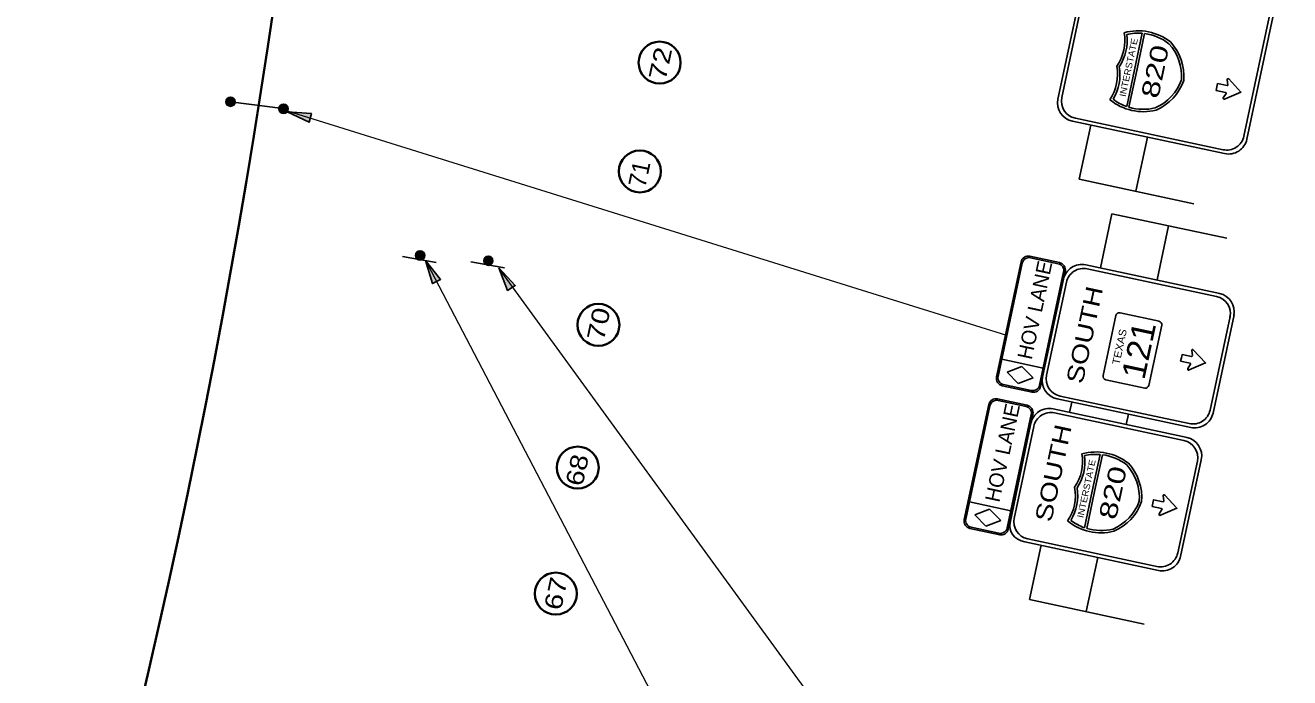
# Model space of a CAD drawing. Extents: x 2363411 to 2369702, y 6977197 to 6988655.
# Drawn here: x 2366110 to 2367124, y 6983553 to 6984077 of the extents above; entities that cross this region are included whole.
import ezdxf
from ezdxf.enums import TextEntityAlignment as Align

# ---------------------------------------------------------------- set-up
doc = ezdxf.new("R2010")
doc.units = 0
doc.header["$LTSCALE"] = 5.6
for name, color, linetype, lineweight in [('1', 7, 'Continuous', 25), ('17', 7, 'Continuous', 35), ('48', 7, 'Continuous', 25)]:
    doc.layers.add(name, color=color, linetype=linetype, lineweight=lineweight)

msp = doc.modelspace()

# ---------------------------------------------------------------- hatches: boundary and pattern name
at = {"layer": '1'}
for points in [[(2366276.795, 6984018.496, 1), (2366272.847, 6984012.162, 1)], [(2366319.296, 6984012.83, 1), (2366315.348, 6984006.496, 1)], [(2366320.148, 6984007.141), (2366337.866, 6983998.922), (2366339.646, 6984005.905)], [(2366428.953, 6983895.063, 1), (2366424.471, 6983889.095, 1)], [(2366430.991, 6983888.125), (2366436.822, 6983869.485), (2366443.188, 6983872.863)], [(2366483.682, 6983890.837, 1), (2366479.199, 6983884.87, 1)], [(2366489.737, 6983882.258), (2366496.901, 6983864.088), (2366503.005, 6983867.917)]]:
    msp.add_hatch(color=256, dxfattribs=at).paths.add_polyline_path(points)

# ---------------------------------------------------------------- linework, layer by layer
for p, q in [((2366937.872, 6984017.444), (2366972.227, 6984178.958)), ((2366941.013, 6984018.692), (2366974.591, 6984176.538)), ((2367120.468, 6984145.521), (2367086.899, 6983987.669)), ((2367123.601, 6984146.769), (2367089.253, 6983985.25)), ((2367005.449, 6984070.162), (2366999.21, 6984040.818)), ((2367007.339, 6984069.953), (2367001.059, 6984040.426)), ((2366992.972, 6984011.475), (2366999.21, 6984040.818)), ((2366994.781, 6984010.878), (2367001.059, 6984040.426)), ((2367065.825, 6984029.94), (2367073.428, 6984028.324)), ((2367074.048, 6984028.904), (2367073.471, 6984033.001)), ((2366274.821, 6984015.329), (2366316.854, 6984009.754)), ((2367070.386, 6984018.494), (2367072.577, 6984022.03)), ((2366949.436, 6983999.656), (2367071.475, 6983973.694)), ((2367070.226, 6983976.833), (2366951.84, 6984002.012)), ((2366954.911, 6983953.23), (2366964.242, 6983996.607)), ((2367000.271, 6983943.473), (2367009.6, 6983986.85)), ((2366954.911, 6983953.23), (2367046.841, 6983933.457)), ((2366981.19, 6983925.466), (2366971.979, 6983882.064)), ((2366981.19, 6983925.466), (2367073.175, 6983905.944)), ((2367026.577, 6983915.833), (2367017.365, 6983872.432)), ((2366412.725, 6983891.166), (2366439.68, 6983886.414)), ((2366467.454, 6983886.94), (2366494.408, 6983882.189)), ((2366960.122, 6983884.518), (2367067.7, 6983861.527)), ((2366925.607, 6983794.815), (2366942.328, 6983872.989)), ((2366961.375, 6983881.384), (2367064.906, 6983859.258)), ((2366928.748, 6983796.06), (2366944.687, 6983870.568)), ((2366984.29, 6983843.899), (2366973.996, 6983795.741)), ((2367018.859, 6983839.378), (2366987.625, 6983846.058)), ((2367075.835, 6983843.158), (2367059.789, 6983768.062)), ((2367079.003, 6983844.551), (2367062.143, 6983765.64)), ((2367010.729, 6983787.892), (2367021.025, 6983836.042)), ((2367037.392, 6983812.757), (2367044.995, 6983811.141)), ((2367045.615, 6983811.721), (2367045.038, 6983815.818)), ((2367041.953, 6983801.311), (2367044.144, 6983804.847)), ((2366976.162, 6983792.405), (2367007.394, 6983785.726)), ((2366937.154, 6983777.017), (2367044.353, 6983754.102)), ((2367043.106, 6983757.244), (2366939.561, 6983779.369)), ((2366947.179, 6983766.183), (2366948.966, 6983774.492)), ((2366933.978, 6983769.004), (2367041.557, 6983746.014)), ((2366935.232, 6983765.871), (2367038.762, 6983743.745)), ((2366992.552, 6983756.486), (2366994.339, 6983764.793)), ((2366899.544, 6983677.747), (2366916.188, 6983757.474)), ((2366902.756, 6983681.165), (2366918.548, 6983755.052)), ((2366971.66, 6983732.475), (2366965.395, 6983703.137)), ((2366973.552, 6983732.265), (2366967.244, 6983702.744)), ((2367049.58, 6983727.061), (2367033.861, 6983653.508)), ((2367052.715, 6983728.307), (2367036.152, 6983650.783)), ((2366959.128, 6983673.801), (2366965.395, 6983703.137)), ((2366960.937, 6983673.201), (2366967.244, 6983702.744)), ((2367022.126, 6983699.32), (2367022.703, 6983695.223)), ((2367013.289, 6983690.717), (2367020.908, 6983689.103)), ((2367021.232, 6983688.349), (2367019.041, 6983684.813)), ((2366911.227, 6983662.462), (2367018.426, 6983639.546)), ((2367017.18, 6983642.688), (2366913.634, 6983664.814)), ((2366915.131, 6983616.302), (2366924.462, 6983659.678)), ((2366960.492, 6983606.545), (2366969.821, 6983649.921)), ((2366915.131, 6983616.302), (2367007.062, 6983596.527))]:
    msp.add_line(p, q, dxfattribs=at)
at = {"layer": '1', "lineweight": 13}
for p, q in [((2366896.921, 6983827.871), (2366320.489, 6984007.69)), ((2366432.524, 6983885.673), (2366722.178, 6983330.158)), ((2366489.804, 6983881.732), (2366764.313, 6983504.552))]:
    msp.add_line(p, q, dxfattribs=at)
at = {"layer": '1'}
for points in [[(2367072.253, 6984022.784), (2367064.634, 6984024.398), (2367065.225, 6984027.17), (2367065.825, 6984029.94)], [(2367074.794, 6984033.592), (2367084.566, 6984023.061), (2367071.353, 6984017.409)], [(2367043.82, 6983805.601), (2367036.201, 6983807.215), (2367036.792, 6983809.987), (2367037.392, 6983812.757)], [(2367046.361, 6983816.409), (2367056.133, 6983805.878), (2367042.92, 6983800.226)], [(2367020.008, 6983683.728), (2367033.221, 6983689.38), (2367023.449, 6983699.911)], [(2367022.083, 6983694.643), (2367014.48, 6983696.259), (2367013.88, 6983693.489), (2367013.289, 6983690.717)]]:
    msp.add_lwpolyline(points, dxfattribs=at)
for points in [[(2366320.148, 6984007.141), (2366337.866, 6983998.922), (2366339.646, 6984005.905)], [(2366430.991, 6983888.125), (2366436.822, 6983869.485), (2366443.188, 6983872.863)], [(2366489.737, 6983882.258), (2366496.901, 6983864.088), (2366503.005, 6983867.917)]]:
    msp.add_lwpolyline(points, close=True, dxfattribs=at)
for centre in [(2366274.821, 6984015.329), (2366317.322, 6984009.663), (2366426.712, 6983892.079), (2366481.441, 6983887.854)]:
    msp.add_circle(centre, 3.732, dxfattribs=at)
at = {"layer": '1', "lineweight": 35}
msp.add_arc((2359877.328, 6985028.058), 6500, 337.9611, 358.49155, dxfattribs=at)
at = {"layer": '1'}
for centre, radius, start, end in [((2366955.483, 6984064.376), 35.984, 325.17475, 10.02506), ((2366955.483, 6984064.376), 37.874, 326.37266, 7.3695), ((2367002.172, 6984030.224), 41.954, 51.85755, 105.55992), ((2367002.172, 6984030.224), 40.064, 85.30399, 103.16874), ((2367002.172, 6984030.224), 40.064, 52.07408, 82.58607), ((2366998.175, 6984035.619), 38.808, 355.8324, 42.47878), ((2366998.175, 6984035.619), 40.698, 355.46626, 42.70216), ((2366949.677, 6984037.075), 35.984, 325.96366, 10.81397), ((2366949.677, 6984037.075), 37.874, 328.61922, 9.61606), ((2367074.225, 6984033.101), 0.759, 42.73196, 188.11309), ((2367000.376, 6984045.972), 38.808, 293.50994, 340.15632), ((2367000.376, 6984045.972), 40.698, 293.28656, 340.52246), ((2367073.552, 6984028.821), 0.506, 257.99346, 7.97657), ((2366952.546, 6984014.322), 15.001, 167.99525, 257.99525), ((2366954.77, 6984015.766), 14.063, 167.99525, 257.99525), ((2367006.223, 6984049.274), 41.954, 230.4288, 284.13117), ((2367006.223, 6984049.274), 40.064, 232.81998, 250.68473), ((2367071.035, 6984018.1), 0.759, 147.87383, 293.25497), ((2367072.162, 6984022.284), 0.506, 328.01036, 77.99346), ((2367006.223, 6984049.274), 40.064, 253.40266, 283.91464), ((2367073.141, 6983990.595), 14.063, 257.99525, 347.99525), ((2367074.585, 6983988.371), 15.001, 257.99525, 347.99525), ((2366956.998, 6983869.854), 15.001, 77.94013, 167.94013), ((2366958.439, 6983867.629), 14.063, 77.94013, 167.94013), ((2367064.196, 6983846.952), 15.001, 347.94013, 77.94013), ((2367061.97, 6983845.51), 14.063, 347.94013, 77.94013), ((2366987.041, 6983843.305), 2.813, 77.93906, 167.93906), ((2367018.269, 6983836.633), 2.813, 347.93906, 77.93906), ((2367045.119, 6983811.638), 0.506, 257.99346, 7.97657), ((2367045.792, 6983815.918), 0.759, 42.73196, 188.11309), ((2367042.602, 6983800.917), 0.759, 147.87383, 293.25497), ((2367043.729, 6983805.101), 0.506, 328.01036, 77.99346), ((2366940.279, 6983791.679), 15.001, 167.94013, 257.94013), ((2366942.504, 6983793.121), 14.063, 167.94013, 257.94013), ((2366976.752, 6983795.152), 2.813, 167.93906, 257.93906), ((2367007.98, 6983788.48), 2.813, 257.93906, 347.93906), ((2366930.854, 6983754.341), 15.001, 77.94013, 167.94013), ((2366932.296, 6983752.116), 14.063, 77.94013, 167.94013), ((2367046.035, 6983771.002), 14.063, 257.94013, 347.94013), ((2367047.477, 6983768.776), 15.001, 257.94013, 347.94013), ((2367035.827, 6983729.997), 14.063, 347.94013, 77.94013), ((2367038.052, 6983731.439), 15.001, 347.94013, 77.94013), ((2366921.69, 6983726.737), 35.984, 325.11963, 9.96995), ((2366921.69, 6983726.737), 37.874, 326.31755, 7.31439), ((2366968.346, 6983692.54), 41.954, 51.80243, 105.50481), ((2366968.346, 6983692.54), 40.064, 85.24888, 103.11363), ((2366968.346, 6983692.54), 40.064, 52.01897, 82.53095), ((2366964.354, 6983697.939), 38.808, 355.77729, 42.42367), ((2366964.354, 6983697.939), 40.698, 355.41114, 42.64704), ((2366915.858, 6983699.442), 35.984, 325.90855, 10.75886), ((2366915.858, 6983699.442), 37.874, 328.56411, 9.56095), ((2367022.88, 6983699.42), 0.759, 42.73196, 188.11309), ((2366966.566, 6983708.29), 38.808, 293.45483, 340.10121), ((2366966.566, 6983708.29), 40.698, 293.23145, 340.46735), ((2367022.207, 6983695.14), 0.506, 257.99346, 7.97657), ((2366916.577, 6983678.565), 14.063, 167.94013, 257.94013), ((2366972.415, 6983711.586), 41.954, 230.37369, 284.07606), ((2366972.415, 6983711.586), 40.064, 232.76486, 250.62962), ((2367019.69, 6983684.419), 0.759, 147.87383, 293.25497), ((2367020.817, 6983688.603), 0.506, 328.01036, 77.99346), ((2366972.415, 6983711.586), 40.064, 253.34754, 283.85953), ((2367020.108, 6983656.446), 14.063, 257.94013, 347.94013), ((2367021.55, 6983654.221), 15.001, 257.94013, 347.94013)]:
    msp.add_arc(centre, radius, start, end, dxfattribs=at)
msp.add_ellipse((2366914.389, 6983675.055), major_axis=(-15.18, 0), ratio=0.848877, start_param=6.07270093, end_param=7.64349725, dxfattribs=at)
at = {"layer": '17'}
for centre in [(2366618.722, 6984046.675), (2366602.887, 6983959.439), (2366569.649, 6983836.392), (2366553.036, 6983721.985), (2366535.489, 6983620.921)]:
    msp.add_circle(centre, 16.828, dxfattribs=at)
at = {"layer": '48'}
for p, q in [((2366888.692, 6983794.628), (2366908.405, 6983886.871)), ((2366889.924, 6983795.12), (2366909.322, 6983885.917)), ((2366915.415, 6983891.412), (2366939.141, 6983886.343)), ((2366938.187, 6983885.417), (2366915.904, 6983890.178)), ((2366942.444, 6983878.838), (2366923.047, 6983788.041)), ((2366943.683, 6983879.332), (2366923.978, 6983787.087)), ((2366892.849, 6983808.809), (2366925.972, 6983801.731)), ((2366897.071, 6983798.41), (2366908.999, 6983802.91)), ((2366918.046, 6983793.928), (2366908.999, 6983802.91)), ((2366906.118, 6983789.427), (2366897.071, 6983798.41)), ((2366906.118, 6983789.427), (2366918.046, 6983793.928)), ((2366893.237, 6983787.615), (2366917.093, 6983782.517)), ((2366894.191, 6983788.544), (2366916.475, 6983783.781)), ((2366862.788, 6983680.234), (2366882.501, 6983772.477)), ((2366864.02, 6983680.726), (2366883.418, 6983771.523)), ((2366889.51, 6983777.018), (2366913.236, 6983771.949)), ((2366912.283, 6983771.022), (2366889.999, 6983775.784)), ((2366916.54, 6983764.444), (2366897.143, 6983673.647)), ((2366917.779, 6983764.938), (2366898.074, 6983672.693)), ((2366866.945, 6983694.415), (2366900.068, 6983687.337)), ((2366871.167, 6983684.016), (2366883.095, 6983688.516)), ((2366880.214, 6983675.033), (2366871.167, 6983684.016)), ((2366880.214, 6983675.033), (2366892.142, 6983679.534)), ((2366892.142, 6983679.534), (2366883.095, 6983688.516)), ((2366867.332, 6983673.221), (2366891.188, 6983668.123)), ((2366868.287, 6983674.15), (2366890.571, 6983669.386))]:
    msp.add_line(p, q, dxfattribs=at)
for centre, radius, start, end in [((2366914.183, 6983885.635), 5.909, 77.93633, 167.93633), ((2366914.751, 6983884.759), 5.54, 77.93633, 167.93633), ((2366937.029, 6983879.995), 5.54, 347.93633, 77.93633), ((2366937.906, 6983880.563), 5.909, 347.93633, 77.93633), ((2366894.472, 6983793.393), 5.909, 167.93575, 257.93575), ((2366895.348, 6983793.961), 5.54, 167.93575, 257.93575), ((2366917.633, 6983789.198), 5.54, 257.93575, 347.93575), ((2366918.201, 6983788.322), 5.909, 257.93575, 347.93575), ((2366888.278, 6983771.241), 5.909, 77.93633, 167.93633), ((2366888.846, 6983770.364), 5.54, 77.93633, 167.93633), ((2366911.124, 6983765.601), 5.54, 347.93633, 77.93633), ((2366912.001, 6983766.168), 5.909, 347.93633, 77.93633), ((2366868.567, 6983678.998), 5.909, 167.93575, 257.93575), ((2366869.444, 6983679.566), 5.54, 167.93575, 257.93575), ((2366891.728, 6983674.804), 5.54, 257.93575, 347.93575), ((2366892.296, 6983673.927), 5.909, 257.93575, 347.93575)]:
    msp.add_arc(centre, radius, start, end, dxfattribs=at)

# ---------------------------------------------------------------- texts
at = {"layer": '1'}
for s, height, rotation, width, p in [('INTERSTATE', 5.198, 77.994, 1.1, (2366992.084, 6984018.943)), ('820', 14.18, 77.994, 1.35, (2367018.158, 6984017.219)), ('TEXAS', 6, 77.939, 1.1, (2366987.124, 6983804.021)), ('121', 18.75, 77.939, 1.1, (2367007.02, 6983791.619)), ('INTERSTATE', 5.198, 77.939, 1.1, (2366958.248, 6983681.271)), ('820', 14.18, 77.939, 1.35, (2366984.316, 6983679.522))]:
    msp.add_text(s, height=height, rotation=rotation, dxfattribs=dict(at, width=width)).set_placement(p)
at = {"layer": '1', "width": 1.25}
for p in [(2366965.83, 6983827.025), (2366940.747, 6983716.194)]:
    msp.add_text('SOUTH', height=13.5, rotation=77.94, dxfattribs=at).set_placement(p, align=Align.CENTER)
at = {"layer": '17'}
for s, width, p in [('72', 1.25, (2366626.144, 6984044.486)), ('70', 1.25, (2366576.657, 6983835.694)), ('68', 1.2, (2366559.472, 6983718.6)), ('67', 1.25, (2366542.36, 6983619.577))]:
    msp.add_text(s, height=14, rotation=77.939, dxfattribs=dict(at, width=width)).set_placement(p, align=Align.CENTER)
msp.add_text('71', height=14, rotation=77.939, dxfattribs=at).set_placement((2366609.298, 6983955.948), align=Align.CENTER)
at = {"layer": '48'}
for p in [(2366925.147, 6983847.033), (2366899.242, 6983732.639)]:
    msp.add_text('HOV LANE', height=11.82, rotation=77.935, dxfattribs=at).set_placement(p, align=Align.CENTER)

doc.saveas('drawing.dxf')
